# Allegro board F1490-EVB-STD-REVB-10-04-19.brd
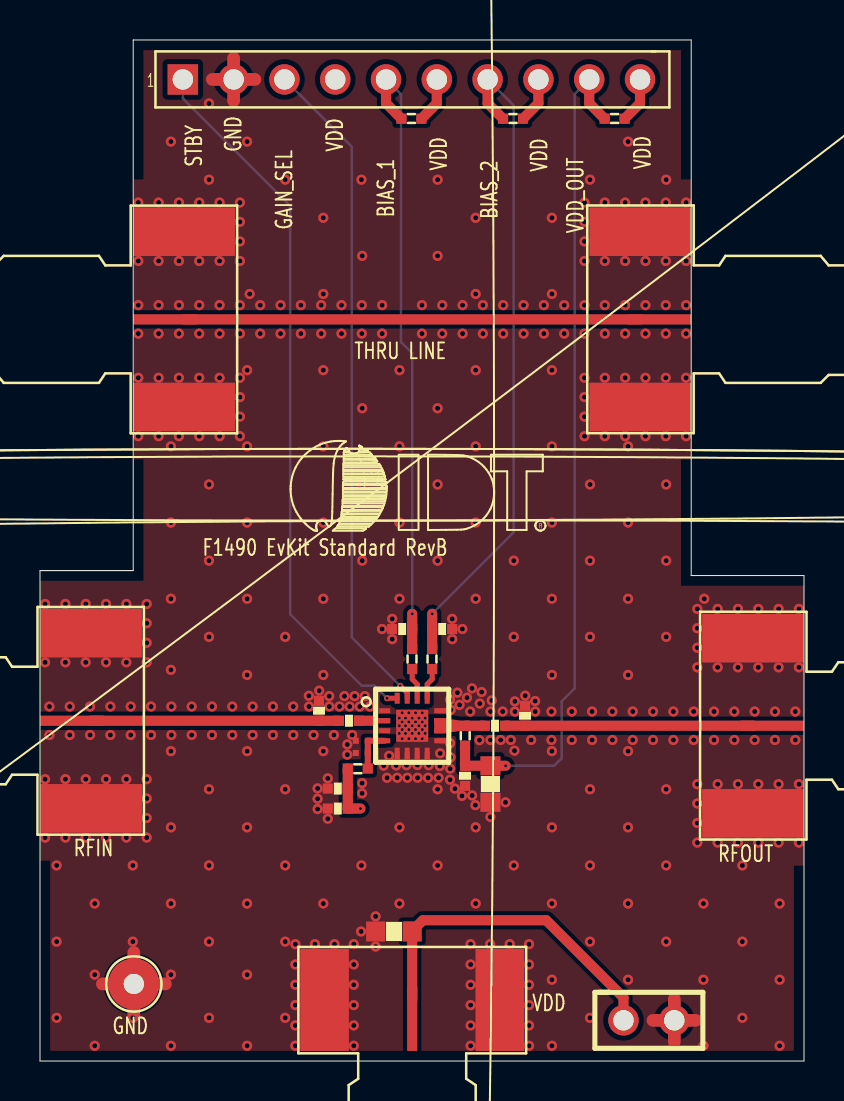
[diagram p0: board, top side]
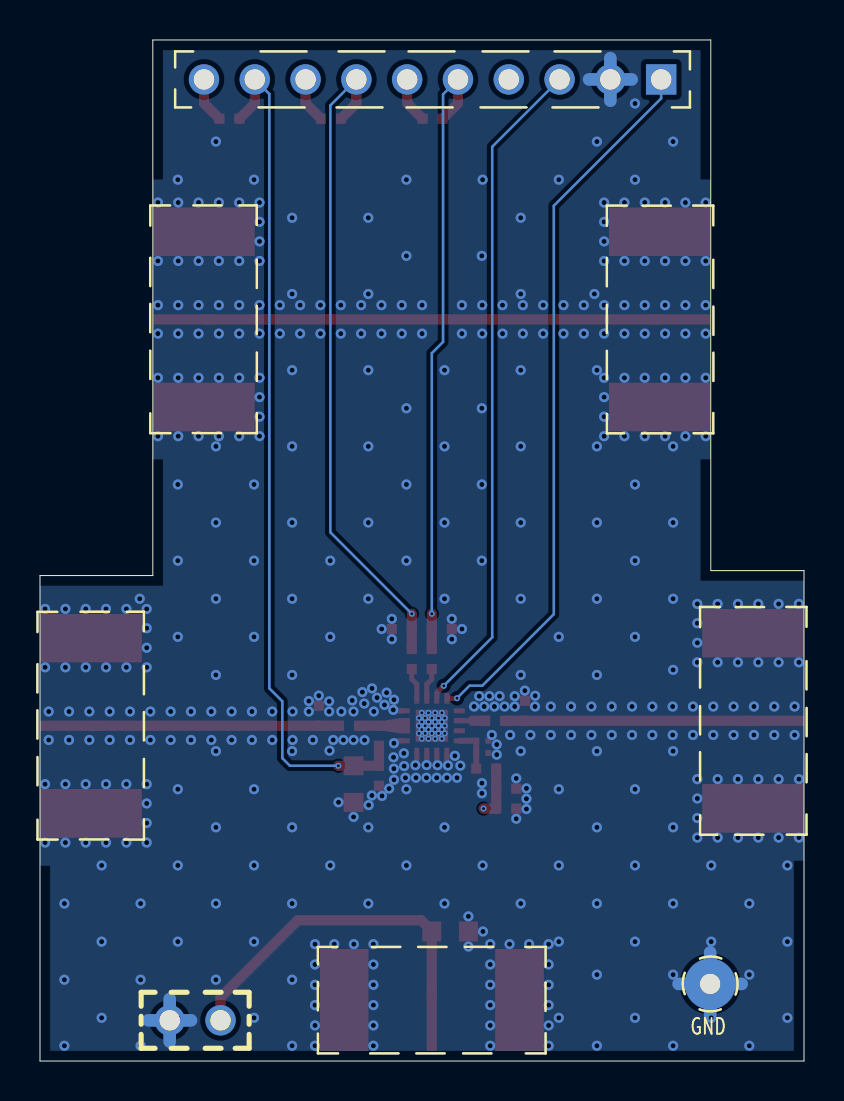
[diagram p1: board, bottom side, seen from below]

Outline 38.2 x 51.05 mm; copper layers: TOP, LAYER_02, LAYER_03, BOTTOM. Coordinates in mm from the lower left corner of the outline.
Outline path: 0,24.52 4.66,24.52 4.66,51.05 32.56,51.05 32.56,24.27 38.2,24.27 38.2,0 0,0 0,24.52

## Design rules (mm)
constraint set DEFAULT: min track width 0.127

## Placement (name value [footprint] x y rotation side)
C1  0.8pF  [CAPC1005N]  13.95 17.51 90 top
C2  10pF  [CAPC1005N]  15.45 17.01 180 top
C3  33pF  [CAPC1005N]  14.89 13.62 180 top
C4  33pF  [CAPC1005N]  14.89 12.62 180 top
C5  22pF  [CAPC1005N]  22.75 16.76 0 top
C6  0.7pF  [CAPC1005N]  24.25 17.26 90 top
C7  33pF  [CAPC1005N]  21.25 14.26 270 top
C8  0.1uF  [CAPC1608N]  22.52 13.85 270 top
C9  33pF  [CAPC1005N]  18.11 21.6 180 top
C10  33pF  [CAPC1005N]  20.11 21.6 0 top
C11  1uF  [CAPC1608N]  17.7 6.48 180 top
C12  2pF  [CAPC0603N]  16.09 16.01 180 top
C13  2pF  [CAPC0603N]  16.09 15.4 180 top
J1  Cinch_142_0701_851  [SMA_JACK_END_LAUNCH_375]  -0.13 17.01 270 top
J2  Cinch_142_0701_851  [SMA_JACK_END_LAUNCH_375]  38.33 16.76 90 top
J3  Cinch_142_0701_851  [SMA_JACK_END_LAUNCH_375]  18.61 0.38 0 top
J4  Cinch_142_0701_851  [SMA_JACK_END_LAUNCH_375]  4.53 37.08 270 top
J5  Cinch_142_0701_851  [SMA_JACK_END_LAUNCH_375]  32.69 37.08 90 top
J6  DNI Headerstrip 1X2  [HEADER_1X2_VERTICAL]  30.45 2.04 0 top
J7  Headerstrip 1X10  [HEADER_1X10_VERTICAL]  18.57 49.08 0 top
L1  1.5nH  [INDC1005N]  15.89 14.62 180 top
L2  1.8nH  [INDC1005N]  21.25 16.26 270 top
NOREF  -  []  4.66 43.43 0 top
NOREF#2  -  []  0 0 0 top
NOREF#3  -  []  4.53 37.02 0 top
NOREF#4  -  []  0 0 90 top
NOREF#5  -  []  -82.26 -104.42 0 top
R1  1.50K  [RESC1005N]  19.61 20.1 90 top
R2  1.00K  [RESC1005N]  18.61 20.1 90 top
R8  DNI_R0402  [RESC1005N]  18.57 47.12 0 top
R9  DNI_R0402  [RESC1005N]  23.65 47.12 0 top
R10  DNI_R0402  [RESC1005N]  28.73 47.12 0 top
TP1  Loop  [TP254_102]  4.69 3.85 0 top
U1  F1490  [QFN-16_EP160]  18.61 16.76 0 top

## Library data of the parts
C1-C7 C9 C10 = CAP_1005N: alternate symbols: (CAPC1005L,CAPC1005RF)
C8 C11 = CAP_1608N
C12 C13 = CAP_0603N
J1-J5 = SMA_EDGE
J6 = HEADER_1X2
J7 = HEADER_1X10
L1 L2 = IND_1005N: alternate symbols: (INDC1005RF)
R1 R2 R8-R10 = RESISTOR_1005N: alternate symbols: (RESC1005RF,RESC1005L,RESC1005M)
TP1 = TESTPOINT
U1 = F1490

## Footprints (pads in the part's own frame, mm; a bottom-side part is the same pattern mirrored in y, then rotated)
CAPC0603N
  rect 0.3x0.3 smd: 1(-0.3,0) 2(0.3,0)
CAPC1005N
  rect 0.508x0.508 smd: 1(-0.5,0) 2(0.5,0)
CAPC1608N
  rect 0.95x1 smd: 1(-0.914,0) 2(0.914,0)
HEADER_1X2_VERTICAL
  round 1.52 hole 1.02: 1(-1.27,0) 2(1.27,0)
HEADER_1X10_VERTICAL
  rect 1.52x1.52 hole 1.02: 1(-11.43,0)
  round 1.52 hole 1.02: 2(-8.89,0) 3(-6.35,0) 4(-3.81,0) 5(-1.27,0) 6(1.27,0) 7(3.81,0) 8(6.35,0) 9(8.89,0) 10(11.43,0)
INDC1005N
  rect 0.508x0.508 smd: 1(-0.5,0) 2(0.5,0)
QFN-16_EP160
  rect 0.55x0.25 smd: 1(-1.375,0.75) 2(-1.375,0.25) 3(-1.375,-0.25) 4(-1.375,-0.75) 9(1.375,-0.75) 10(1.375,-0.25) 11(1.375,0.25) 12(1.375,0.75)
  rect 0.25x0.55 smd: 5(-0.75,-1.375) 6(-0.25,-1.375) 7(0.25,-1.375) 8(0.75,-1.375) 13(0.75,1.375) 14(0.25,1.375) 15(-0.25,1.375) 16(-0.75,1.375)
  rect 1.6x1.6 smd: EP(0,0)
RESC1005N
  rect 0.508x0.508 smd: 1(-0.5,0) 2(0.5,0)
SMA_JACK_END_LAUNCH_375
  rect 0.508x3.175 smd: 1(0,2.667)
  rect 2.413x5.08 smd: 2(-4.381,2.667) 3(4.381,2.667) 4(-4.381,2.667) 5(4.381,2.667)
TP254_102
  round 2.54 hole 1.01: 1(0,0)

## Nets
GND: C1.2(B) C3.2(B) C4.2(B) C6.2(B) C7.2(B) C8.2(B) C9.2(B) C10.2(B) C11.2(B) C12.2(B) C13.2(B) J1.2 J1.3 J1.4 J1.5 J2.2 J2.3 J2.4 J2.5 J3.2 J3.3 J3.4 J3.5 J4.2 J4.3 J4.4 J4.5 J5.2 J5.3 J5.4 J5.5 J6.2 J7.2 TP1.1 U1.1 U1.3 U1.5 U1.6 U1.7 U1.8 U1.9 U1.12 U1.EP
VDD: C3.1 C4.1 C11.1 J3.1 J6.1 J7.4 J7.6 J7.8 J7.10 L1.2(B) R8.2 R9.2 R10.2
GAIN_SEL: J7.3 U1.15
STBY: J7.1 U1.16
N963622: C5.1 L2.1 U1.10 U1.11
N973158: J4.1 J5.1
N977718: C1.1 C2.2(B) J1.1
N995247: C12.1 C13.1 L1.1 U1.4(VDD1)
N996909: C7.1 C8.1 J7.9 L2.2(B) R10.1
N1050153: C2.1 U1.2
N1050802: C5.2(B) C6.1 J2.1
N1055643: C10.1 J7.7 R1.2 R9.1
N1055675: R2.1 U1.14
N1058474: C9.1 J7.5 R2.2 R8.1
N1082898: R1.1 U1.13

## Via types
v1: diameter 0.305, hole 0.152, TOP to BOTTOM, 37 vias
v2: diameter 0.508, hole 0.254, TOP to BOTTOM, 458 vias

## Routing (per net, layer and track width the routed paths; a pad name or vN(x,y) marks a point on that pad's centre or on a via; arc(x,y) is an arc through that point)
GND: length 60.7
  TOP w0.25: v2(19.43,14.79) 19.36,14.86 U1.8 ; U1.5 17.86,14.83 v2(17.81,14.78) ; v2(18.87,14.8) 18.86,14.81 U1.7 ; v2(20.54,17.56) 20.4,17.56 20.36,17.51 U1.12 ; U1.6 18.36,14.82 v2(18.33,14.79) ; v2(20.51,15.89) 20.47,15.92 20.42,15.92 20.33,16.01 U1.9
  TOP w0.627: J6.2 32.78,2.04 ; J6.2 31.72,0.97 ; J6.2 31.72,3.1 ; J6.2 30.65,2.04 ; J7.2 9.68,50.15 ; J7.2 8.62,49.08 ; J7.2 9.68,48.02 ; J7.2 10.75,49.08 ; 4.69,2.28 TP1.1 ; TP1.1 4.69,5.43 ; TP1.1 6.27,3.85 ; TP1.1 3.12,3.85
  LAYER_02 w0.627: J6.2 31.72,3.1 ; J6.2 32.78,2.04 ; J6.2 30.65,2.04 ; J6.2 31.72,0.97 ; J7.2 10.75,49.08 ; J7.2 9.68,48.02 ; J7.2 8.62,49.08 ; J7.2 9.68,50.15 ; TP1.1 6,3.85 ; TP1.1 4.69,2.55 ; TP1.1 4.69,5.16 ; TP1.1 3.39,3.85
  LAYER_03 w0.627: TP1.1 4.69,5.16 ; TP1.1 3.39,3.85 ; TP1.1 4.69,2.55 ; TP1.1 6,3.85 ; 31.72,0.97 J6.2 ; J6.2 32.78,2.04 ; J6.2 31.72,3.1 ; J6.2 30.65,2.04 ; 9.68,48.02 J7.2 ; J7.2 9.68,50.15 ; J7.2 10.75,49.08 ; J7.2 8.62,49.08
  BOTTOM w0.627: J6.2 32.78,2.04 ; J6.2 31.72,0.97 ; J6.2 30.65,2.04 ; J6.2 31.72,3.1 ; 8.62,49.08 J7.2 ; J7.2 9.68,48.02 ; J7.2 10.75,49.08 ; J7.2 9.68,50.15 ; 4.69,2.28 TP1.1 ; TP1.1 3.12,3.85 ; TP1.1 6.27,3.85 ; TP1.1 4.69,5.43
  vias: v1(17.97,17.15) v1(17.97,16.76) v1(17.97,16.38) v1(18.11,17.41) v1(18.11,16.96) v1(18.11,16.57) v1(18.11,16.12) v1(18.28,17.15) v1(18.28,16.76) v1(18.28,16.38) v1(18.44,17.41) v1(18.44,16.96) v1(18.44,16.57) v1(18.44,16.12) v1(18.61,17.15) v1(18.61,16.76) v1(18.61,16.38) v1(18.78,17.41) v1(18.78,16.96) v1(18.78,16.57) v1(18.78,16.12) v1(18.95,17.15) v1(18.95,16.76) v1(18.95,16.38) v1(19.11,17.41) v1(19.11,16.96) v1(19.11,16.57) v1(19.11,16.12) v1(19.26,17.15) v1(19.26,16.76) v1(19.26,16.38) v2(0.25,22.86) v2(0.25,19.93) v2(0.25,14.09) v2(0.25,11.17) v2(0.47,17.73) v2(0.47,16.3) v2(0.83,9.78) v2(0.83,5.97) v2(0.83,2.16) v2(1.27,22.86) v2(1.27,19.93) v2(1.27,14.09) v2(1.27,11.17) v2(1.49,17.73) v2(1.49,16.3) v2(2.29,22.86) v2(2.29,19.93) v2(2.29,14.09) v2(2.29,11.17) v2(2.5,17.73) v2(2.5,16.3) v2(2.74,7.87) v2(2.74,4.32) v2(2.74,0.76) v2(3.3,22.86) v2(3.3,19.93) v2(3.3,14.09) v2(3.3,11.17) v2(3.52,17.73) v2(3.52,16.3) v2(4.32,22.86) v2(4.32,19.93) v2(4.32,14.09) v2(4.32,11.17) v2(4.54,17.73) v2(4.54,16.3) v2(4.64,9.78) v2(4.64,5.97) v2(4.64,2.16) v2(4.92,42.93) v2(4.92,40) v2(4.92,37.8) v2(4.92,36.37) v2(4.92,34.16) v2(4.92,31.24) v2(5.33,22.86) v2(5.33,21.89) v2(5.33,20.91) v2(5.33,19.93) v2(5.33,14.09) v2(5.33,13.13) v2(5.33,12.15) v2(5.33,11.17) v2(5.55,17.73) v2(5.55,16.3) v2(5.93,42.93) v2(5.93,40) v2(5.93,37.8) v2(5.93,36.37) v2(5.93,34.16) v2(5.93,31.24) v2(6.55,45.97) v2(6.55,30.73) v2(6.55,26.92) v2(6.55,23.11) v2(6.55,19.56) v2(6.55,15.49) v2(6.55,11.68) v2(6.55,7.87) v2(6.55,4.32) v2(6.55,0.76) v2(6.57,17.73) v2(6.57,16.3) v2(6.95,42.93) v2(6.95,40) v2(6.95,37.8) v2(6.95,36.37) v2(6.95,34.16) v2(6.95,31.24) v2(7.58,17.73) v2(7.58,16.3) v2(7.96,42.93) v2(7.96,40) v2(7.96,37.8) v2(7.96,36.37) v2(7.96,34.16) v2(7.96,31.24) v2(8.45,47.88) v2(8.45,44.07) v2(8.45,28.83) v2(8.45,25.02) v2(8.45,21.21) v2(8.45,13.59) v2(8.45,9.78) v2(8.45,5.97) v2(8.45,2.16) v2(8.6,17.73) v2(8.6,16.3) v2(8.98,42.93) v2(8.98,40) v2(8.98,37.8) v2(8.98,36.37) v2(8.98,34.16) v2(8.98,31.24) v2(9.62,17.73) v2(9.62,16.3) v2(10,42.93) v2(10,41.96) v2(10,40.98) v2(10,40) v2(10,37.8) v2(10,36.37) v2(10,34.16) v2(10,33.2) v2(10,32.22) v2(10,31.24) v2(10.36,45.97) v2(10.36,34.54) v2(10.36,30.73) v2(10.36,26.92) v2(10.36,23.11) v2(10.36,19.3) v2(10.36,15.49) v2(10.36,11.68) v2(10.36,7.87) v2(10.36,4.32) v2(10.36,0.76) v2(10.48,38.35) v2(10.63,17.73) v2(10.63,16.3) v2(11.01,37.8) v2(11.01,36.37) v2(11.65,17.73) v2(11.65,16.3) v2(12.03,37.8) v2(12.03,36.37) v2(12.26,44.07) v2(12.26,21.21) v2(12.26,13.59) v2(12.26,9.78) v2(12.26,5.97) v2(12.26,2.16) v2(12.66,17.73) v2(12.66,16.3) v2(12.77,5.84) v2(12.77,4.83) v2(12.77,3.81) v2(12.77,2.79) v2(12.77,1.78) v2(12.77,0.76) v2(13.04,37.8) v2(13.04,36.37) v2(13.44,18.26) v2(13.45,17.73) v2(13.68,16.3) v2(13.75,5.84) v2(13.96,18.52) v2(13.88,13.63) v2(13.88,13.12) v2(13.88,12.6) v2(14.06,37.8) v2(14.06,36.37) v2(14.17,42.16) v2(14.17,38.35) v2(14.17,34.54) v2(14.17,30.73) v2(14.17,26.92) v2(14.17,23.11) v2(14.17,19.3) v2(14.17,15.49) v2(14.17,7.87) v2(14.39,14.13) v2(14.39,12.11) v2(14.46,18.24) v2(14.47,17.73) v2(14.7,16.3) v2(14.72,5.84) v2(14.98,17.73) v2(15.08,37.8) v2(15.08,36.37) v2(15.22,18.24) v2(15.37,15.83) v2(15.37,15.32) v2(15.48,17.73) v2(15.61,16.3) v2(15.73,18.24) v2(15.69,5.84) v2(15.69,4.83) v2(15.69,3.81) v2(15.69,2.79) v2(15.69,1.78) v2(15.69,0.76) v2(15.99,17.73) v2(16.05,6.48) v2(16.07,44.07) v2(16.11,40.26) v2(16.09,37.8) v2(16.09,36.37) v2(16.11,32.64) v2(16.11,28.83) v2(16.11,25.02) v2(16.11,13.89) v2(16.11,13.39) v2(16.07,9.78) v2(16.24,18.24) v2(16.5,17.73) v2(16.78,7.23) v2(16.78,5.72) v2(17.11,37.8) v2(17.11,36.37) v2(17.1,21.6) v2(17.19,14.77) v2(17.35,14.16) v2(17.46,15.26) v2(17.61,22.11) v2(17.61,21.09) v2(17.86,14.16) v2(17.98,34.54) v2(17.98,30.73) v2(17.98,26.92) v2(17.98,23.11) v2(17.98,11.68) v2(17.98,7.87) v2(18.37,14.16) v2(18.88,14.16) v2(19.1,37.8) v2(19.1,36.37) v2(19.4,14.16) v2(19.88,44.07) v2(19.88,40.26) v2(19.88,32.64) v2(19.88,28.83) v2(19.88,25.02) v2(19.93,14.16) v2(19.88,13.59) v2(19.88,9.78) v2(20.01,15.39) v2(19.99,14.75) v2(20.11,37.8) v2(20.11,36.37) v2(20.5,18.06) v2(20.53,15.19) v2(20.51,14.62) v2(20.5,14.06) v2(20.61,22.11) v2(20.61,21.09) v2(20.75,13.62) v2(20.87,18.42) v2(20.98,17.81) v2(21.13,37.8) v2(21.13,36.37) v2(21.12,21.6) v2(21.1,13.26) v2(21.35,18.17) v2(21.51,17.48) v2(21.53,5.84) v2(21.53,4.83) v2(21.53,3.81) v2(21.53,2.79) v2(21.53,1.78) v2(21.53,0.76) v2(21.6,18.63) v2(21.61,13.28) v2(21.79,42.16) v2(21.79,38.35) v2(21.79,34.54) v2(21.79,30.73) v2(21.79,26.92) v2(21.79,23.11) v2(21.77,12.79) v2(21.79,11.68) v2(21.79,7.87) v2(21.99,17.87) v2(21.97,16.04) v2(22.15,37.8) v2(22.15,36.37) v2(22.08,18.45) v2(22.53,17.48) v2(22.53,16.05) v2(22.52,12.21) v2(22.51,5.84) v2(22.59,18.03) v2(23.03,16.05) v2(23.14,17.48) v2(23.16,37.8) v2(23.16,36.37) v2(23.28,12.93) v2(23.54,16.05) v2(23.49,5.84) v2(23.69,25.02) v2(23.69,21.21) v2(23.74,17.98) v2(23.75,17.48) v2(23.72,15.52) v2(23.69,9.78) v2(24.18,37.8) v2(24.18,36.37) v2(24.26,18.27) v2(24.45,5.84) v2(24.45,4.83) v2(24.45,3.81) v2(24.45,2.79) v2(24.45,1.78) v2(24.45,0.76) v2(24.56,16.05) v2(24.76,18) v2(24.76,17.48) v2(25.19,37.8) v2(25.19,36.37) v2(25.6,42.16) v2(25.6,38.35) v2(25.6,34.54) v2(25.6,30.73) v2(25.6,26.92) v2(25.6,23.11) v2(25.6,19.3) v2(25.57,17.48) v2(25.57,16.05) v2(25.6,15.49) v2(25.6,11.68) v2(25.6,7.87) v2(25.6,4.06) v2(25.6,0.76) v2(26.21,37.8) v2(26.21,36.37) v2(26.59,17.48) v2(26.59,16.05) v2(27.23,42.93) v2(27.23,41.96) v2(27.23,40.98) v2(27.23,40) v2(27.23,37.8) v2(27.23,36.37) v2(27.23,34.16) v2(27.23,33.2) v2(27.23,32.22) v2(27.23,31.24) v2(27.5,44.07) v2(27.5,28.83) v2(27.5,25.02) v2(27.5,21.21) v2(27.5,13.59) v2(27.5,9.78) v2(27.5,5.97) v2(27.5,2.16) v2(27.61,17.48) v2(27.61,16.05) v2(28.24,42.93) v2(28.24,40) v2(28.24,37.8) v2(28.24,36.37) v2(28.24,34.16) v2(28.24,31.24) v2(28.62,17.48) v2(28.62,16.05) v2(29.26,42.93) v2(29.26,40) v2(29.26,37.8) v2(29.26,36.37) v2(29.26,34.16) v2(29.26,31.24) v2(29.41,45.97) v2(29.41,30.73) v2(29.41,26.92) v2(29.41,23.11) v2(29.41,19.3) v2(29.41,15.49) v2(29.41,11.68) v2(29.41,7.87) v2(29.41,4.06) v2(29.64,17.48) v2(29.64,16.05) v2(30.27,42.93) v2(30.27,40) v2(30.27,37.8) v2(30.27,36.37) v2(30.27,34.16) v2(30.27,31.24) v2(30.65,17.48) v2(30.65,16.05) v2(31.31,44.07) v2(31.29,42.93) v2(31.29,40) v2(31.29,37.8) v2(31.29,36.37) v2(31.29,34.16) v2(31.29,31.24) v2(31.31,28.83) v2(31.31,25.02) v2(31.31,21.21) v2(31.31,13.59) v2(31.31,9.78) v2(31.31,5.97) v2(31.31,2.16) v2(31.67,17.48) v2(31.67,16.05) v2(32.31,42.93) v2(32.31,40) v2(32.31,37.8) v2(32.31,36.37) v2(32.31,34.16) v2(32.31,31.24) v2(32.69,17.48) v2(32.69,16.05) v2(32.87,22.61) v2(32.87,21.64) v2(32.87,20.66) v2(32.87,19.68) v2(32.87,13.84) v2(32.87,12.88) v2(32.87,11.9) v2(32.87,10.92) v2(33.22,23.11) v2(33.17,7.87) v2(33.17,4.06) v2(33.17,0.76) v2(33.7,17.48) v2(33.7,16.05) v2(33.88,22.61) v2(33.88,19.68) v2(33.88,13.84) v2(33.88,10.92) v2(34.72,17.48) v2(34.72,16.05) v2(34.9,22.61) v2(34.9,19.68) v2(34.9,13.84) v2(34.9,10.92) v2(35.12,9.78) v2(35.12,5.97) v2(35.12,2.16) v2(35.73,17.48) v2(35.73,16.05) v2(35.92,22.61) v2(35.92,19.68) v2(35.92,13.84) v2(35.92,10.92) v2(36.75,17.48) v2(36.75,16.05) v2(36.93,22.61) v2(36.93,19.68) v2(36.93,13.84) v2(36.93,10.92) v2(36.98,7.87) v2(36.98,4.06) v2(36.98,0.76) v2(37.77,17.48) v2(37.77,16.05) v2(37.95,22.61) v2(37.95,19.68) v2(37.95,13.84) v2(37.95,10.92)
VDD: length 26.5
  TOP w0.508: L1.2 C3.1 C4.1 v1(16.02,12.62) ; R8.2 19.84,47.89 J7.6 ; J7.10 30,47.89 R10.2 ; J7.8 24.92,47.89 R9.2 ; J6.1 29.18,3.18 25.31,7.04 19.15,7.04 18.61,6.5 C11.1 J3.1
GAIN_SEL: length 33.5
  TOP w0.25: U1.15 18.36,18.41 v1(18.01,18.76)
  BOTTOM w0.127: J7.3 15.59,45.72 15.59,21.18 v1(18.01,18.76)
STBY: length 36.1
  TOP w0.25: U1.16 v1(17.35,18.14)
  BOTTOM w0.127: v1(17.35,18.14) 16.72,18.77 16.08,18.77 12.51,22.34 12.51,42.76 7.14,48.13 J7.1
N963622: length 1
  TOP w0.508: C5.1 L2.1
N973158: length 22.8
  TOP w0.508: J5.1 J4.1
N977718: length 12.4
  TOP w0.508: J1.1 C1.1 C2.2
N995247: length 2.2
  TOP w0.3: L1.1 C13.1 C12.1 U1.4
N996909: length 42.8
  TOP w0.508: J7.9 27.46,47.89 R10.1 ; L2.2 C7.1 C8.1 v1(23.28,14.76)
  BOTTOM w0.127: v1(23.28,14.76) 25.71,14.76 26.09,15.14 26.09,17.99 26.73,18.64 26.73,48.35 J7.9
N1050802: length 12.4
  TOP w0.508: J2.1 C6.1 C5.2
N1055643: length 33
  TOP w0.508: R1.2 C10.1 v1(19.61,22.36) ; R9.1 22.38,47.89 J7.7
  BOTTOM w0.127: J7.7 23.68,47.78 23.68,26.44 v1(19.61,22.36)
N1055675: length 1.6
  TOP w0.25: R2.1 18.61,19.09 18.86,18.84 U1.14
N1058474: length 31.3
  TOP w0.508: R8.1 17.3,47.89 J7.5 ; R2.2 C9.1 v1(18.61,22.36)
  BOTTOM w0.127: J7.5 18.05,48.34 18.05,35.96 18.61,35.39 v1(18.61,22.36)
N1082898: length 1.6
  TOP w0.25: U1.13 19.36,18.84 19.61,19.09 R1.1

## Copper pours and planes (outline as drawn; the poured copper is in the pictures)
GND on TOP, BOTTOM, LAYER_02, LAYER_03: 0.51,0.51 37.69,0.51 37.69,9.76 38.2,9.76 38.2,23.76 32.05,23.76 32.05,30.08 32.56,30.08 32.56,44.08 32.05,44.08 32.05,50.55 5.17,50.55 5.17,44.08 4.66,44.08 4.66,30.08 5.17,30.08 5.17,24.01 0,24.01 0,10.01 0.51,10.01
VDD on LAYER_03: 12.13,11.02 26.44,11.02 26.44,1.12 30.13,1.12 30.13,15.02 25.6,15.02 25.6,47.7 31.19,47.7 31.19,50.2 13.48,50.2 13.48,47.94 15.65,47.94 15.65,20.05 12.13,20.05
N963622 on TOP (solid shape): 21.51,16.93 21.51,16.59 20.26,16.39 19.71,16.39 19.71,17.14 20.26,17.14

Small or netless copper shapes (teardrops, artwork), in the pictures only: 1 on TOP

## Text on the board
Ref Des/Silkscreen Bottom: GND
User.Comments: 1. WHEN MOUNTING CONNECTORS, MAKE SURE THE CONNECTOR | ASSEMBLY NOTES: UNLESS OTHERWISE SPECIFIED | THE PCB EDGE. NO AIR GAP. | PIN IS CENTERED ON RF TRACE AND THEY ARE FLUSH AGAINST
Ref Des/Silkscreen Top: RFIN | GND | F1490 EvKit Standard RevB | THRU LINE | VDD | RFOUT | STBY | GAIN_SEL | BIAS_1 | BIAS_2 | VDD_OUT
XSECTION_CHART: *  SURFACE - AIR 0 MIL | L1 TOP CONDUCTOR - COPPER 1.5 OZ - FINISHED CU | *  DIELECTRIC - ROGERS 4003C 12 MIL | L2 LAYER_02 CONDUCTOR - COPPER 1/2 OZ | *  DIELECTRIC - FR-4 FILL (32.4 MIL REFERENCE) | L3 LAYER_03 CONDUCTOR - COPPER 1/2 OZ | *  DIELECTRIC - FR-4 12 MIL | L4 BOTTOM CONDUCTOR - COPPER 1.5 OZ - FINISHED CU | DESIGN CROSS SECTION CHART | ___________________________ | TOTAL THICKNESS 62 MILS +/- 6 MILS | 1-4
DIMENSION: 22.DO NOT USE BREAK-AWAY TABS OR V-SCORING AT SMA CONNECTOR LOCATIONS. (J1-J3, J5-J6) | 13.OVERALL THICKNESS OF PCB SHALL NOT EXCEED 68 MILS. | 14.BOARD TYPE: MULTILAYER. | 15.FINISHED BOARD THICKNESS AND CONSTRUCTION SPECIFIED IN STACK-UP. | 16.COPPER WEIGHT: SPECIFIED IN STACK-UP. | 17.DO NOT MODIFY DATA TO PULLBACK AREAS OF METAL THAT EXTEND ALL THE WAY TO THE | 18.WARP AND TWIST OF BOARD SHALL NOT EXCEED 1%. | 19.REMOVE ALL BURRS AND BREAK SHARP EDGES. | 20.TEST REQUIREMENTS: | 21.FILL ALL THE VIAS WITH NON-CONDUCTIVE EPOXY AND PLANARIZE THE SURFACE. | TDR TEST REQUIRED AND RESULTS TO BE DELIVERED. | 12.RoHS COMPLIANT. | 9. SOLDERABILITY: SOLDERABILITY TO BE CONFIRMED PER LOT IAW IPC-650. | 10.SERIALIZE BOARDS AS FOLLOWS: S/N:YYYYMM-### (YEAR, MONTH-NUMBER). | 11.IMPEDANCE CONTROL: 20 MIL TRACES ON LAYER 1 (TOP) ARE CPWG 50 OHMS +/-10%. | VENDOR TO ADJUST 20 MIL LINEWIDTH OR 8 MIL GAP VALUES TO SUIT PROCESS. | IN IPC-D-356 FORMAT. FINAL PRODUCT TO BE TESTED TRACEABLE TO SAME. | 1. APPLICABLE SPECIFICATIONS AND ORDER OF PRECEDENCE: | - THE PURCHASE ORDER | - THIS DRAWING | - IPC-6010 SERIES, CURRENT REVISION, CLASS 2 | - IPC-A-600 CURRENT REVISION, CLASS 2 | 2. MATERIAL: ROGERS 4003C WITH FR4. COPPER THICKNESS, DIELECTRIC ARRANGEMENT AND | THICKNESS PER REFERENCE STACKUP AND REQUIREMENTS BELOW. FLAMMABILITY | RATING UL 94VO REQUIRED. | 3. PLATING: ADDITIONAL CU PLATE APPROX 1OZ/SQFT. PLATED THROUGH HOLES AS | SHOWN IN CHART REQUIRE 0.001" MINIMUM BARREL PLATING THICKNESS. | 4. SURFACE FINISH: ELECTROLESS NICKEL/IMMERSION GOLD PER IPC-4552. NICKEL | THICKNESS 120-240 MICRO-INCHES. GOLD THICKNESS 3-6 MICRO-INCHES. | 5. SOLDERMASK: LPI SOLDERMASK SMOBC BOTH SIDES PER IPC-SM-840 CURRENT | ENCROACH ON SMD LANDS. COLOR GREEN, MATTE FINISH. | 6. SILKSCREEN: APPLY WHITE, NON-CONDUCTIVE/NON-NUTRIENT EPOXY INK PER | ARTWORK SUPPLIED. ENSURE NO LEGEND IS APPLIED OVER SOLDERABLE | SURFACES. MARK LOGO, UL RATING AND DATE CODE ON SECONDARY SIDE (BOTTOM). | 7. ARTWORK: BOARD IS DESIGNED TO MINIMAL 6/6 TECHNOLOGY. | 8. NETLIST TEST: VENDOR TO PROVE TOOLED GERBER FILES AGAINST SUPPLIED NETLIST | REVISION CLASS H AND ARTWORKS SUPPLIED. ENSURE SOLDERMASK DOES NOT | FABRICATION NOTES: | PCB EDGE. THIS IS A CRITICAL REQUIREMENT. EXPOSED COPPER IS ACCEPTABLE. | 100% NETLIST ELECTRICAL VERIFICATION USING SUPPLIED IPC-D-356 NETLIST FOR OPENS AND SHORTS. | SEE NOTE 17: 5 PLACES
User.28: FIGURE | FINISHED_SIZE | 6.0 | 10.0 | 39.76 | 40.16 | DRILL CHART: TOP to BOTTOM | ALL UNITS ARE IN MILS | TOLERANCE_DRILL | +3.0/-6.0 | +0.0/-0.0 | +3.0/-3.0 | PLATED | QTY | 36 | 459 | 1 | 12 | 508 | TOTAL HOLES:
